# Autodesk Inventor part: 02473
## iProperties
Author: Administrator
Shininess: 64.0
Angle Display Precision: 2
Document Length Units: 11272
Document Angle Units: 11286
Document Time Units: 11279
Document Mass Units: 11290
Document Length Units Precision: 3
Document Angle Units Precision: 2
Compacted: True
PropertySet Name: _Private Model Information
Created: 2002-04
Part Number: 02473
Material: Stainless Steel, 440C
Document SubType Name: Modeling
Designer: Administrator
Control State: 0
Master: False
Checked Out: False
PropertySet Name: Design Tracking Control
Density: 0.0
Volumn: 0.0
Area: 0.0
PropertySet Name: Model Information
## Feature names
1. Revolution1
